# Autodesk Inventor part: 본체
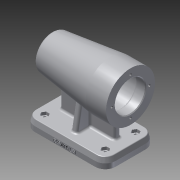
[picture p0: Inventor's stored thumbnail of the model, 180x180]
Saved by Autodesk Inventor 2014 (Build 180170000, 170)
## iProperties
Created: 2017-01
Part Number: 본체
Material: Aluminum 6061
Document SubType Name: Modeling
Designer: user
Density: 2.71 g/cm^3
Appearance: Aluminum - Flat
Mass: 797.096 g
Surface Area: 656.654 cm^2
Volume: 294.131 cm^3
Author: user
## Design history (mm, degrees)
sketch "Sketch1"
  geometry: L1 (-42, 35)-(42, 35); L2 (56, 21)-(56, -21); L3 (42, -35)-(-42, -35); L4 (-56, -21)-(-56, 21); L5 (-56, 35)-(56, -35); L6 (56, 35)-(-56, -35); A1 r 14 centre (-42, 21) between (-42, 35) and (-56, 21); A2 r 14 centre (-42, -21) between (-56, -21) and (-42, -35); A3 r 14 centre (42, -21) between (42, -35) and (56, -21); A4 r 14 centre (42, 21) between (56, 21) and (42, 35); 1 further point
  constraints: 12 end point, 8 point on circle, 8 point on line, 8 tangent, 4 centre point, 3 equal radius, 2 midpoint, 2 parallel, 1 horizontal, 1 perpendicular
  dimensions: "d0" = 112 distance of L5.end L6.end; "d1" = 70 distance of L6.start L5.end; "d2" = 14 radius of A1
extrude "Extrusion1" new body sketch "Sketch1" distance "d3" = 7; taper "d4" = 0 deg
sketch "Sketch2"
  geometry: L1 (56, -21)-(56, 21) reference; L2 (42, 35)-(-42, 35) reference; L3 (-56, 21)-(-56, -21) reference; L4 (-42, -35)-(42, -35) reference; A1 r 14 centre (42, 21) between (56, 21) and (42, 35) reference; A2 r 14 centre (-42, 21) between (-42, 35) and (-56, 21) reference; A3 r 14 centre (-42, -21) between (-56, -21) and (-42, -35) reference; A4 r 14 centre (42, -21) between (42, -35) and (56, -21) reference; 1 further point
extrude "Extrusion2" join sketch "Sketch2" distance "d5" = 7; taper "d6" = -15 deg
workplane "Work Plane1"
sketch "Sketch4"
  geometry: L1 (98, 0)-(98, 7) reference; L2 (98, 40)-(98, 108) reference; L3 (98, 108)-(70, 108); L4 (70, 108)-(184.9, 108); L5 (98, 74)-(-14, 74); L6 (70, 108)-(-10.27, 98.144); L7 (-14, 74)-(-14, 74.122); L8 (98, 0)-(84, 0) reference; A1 r 80 centre (66, 74) between (-10.27, 98.144) and (-14, 74); 1 further point
  constraints: 12 end point, 2 perpendicular, 2 point on circle, 1 centre point, 1 collinear, 1 horizontal, 1 midpoint, 1 point on line, 1 tangent, 1 vertical
  dimensions: "d7" = 68 distance of L2.start L2.end; "d8" = 28 distance of L2.end L3.end; "d11" = 160 diameter of A1; "d14" = 74 distance from line of L8 L5.start
revolve "Revolution1" sketch "Sketch4" stored, may be unused: angle "d12" = 90 deg
fillet "Fillet1" dims "d13" = 3
sketch "Sketch5"
  geometry: L1 (42, -33.124)-(-42, -33.124) reference; L2 (-4, 23)-(4, 23); L3 (4, 23)-(4, 4); L4 (4, 4)-(38, 4); L5 (38, 4)-(38, -4); L6 (38, -4)-(4, -4); L7 (4, -4)-(4, -23); L8 (4, -23)-(-4, -23); L9 (-4, -23)-(-4, -4); L10 (-4, -4)-(-38, -4); L11 (-38, -4)-(-38, 4); L12 (-38, 4)-(-4, 4); L13 (-4, 4)-(-4, 23); L14 (56, -21)-(56, 21) reference; L15 (42, 35)-(-42, 35) reference; L16 (-56, 21)-(-56, -21) reference; L17 (-42, -35)-(42, -35) reference; 1 further point
  constraints: 24 end point, 9 parallel, 3 perpendicular
  dimensions: "d15" = 8 distance of L2.start L2.end; "d16" = 8 distance of L4.end L5.end; "d17" = 8 distance of L7.end L8.end; "d18" = 8 distance of L10.end L11.end; "d19" = 52 distance from line of L14 L2.end; "d20" = 31 distance between parallel lines of L15 L4; "d21" = 31 distance between parallel lines of L15 L12; "d22" = 52 distance between parallel lines of L14 L7; "d23" = 18 distance between parallel lines of L16 L11; "d24" = 18 distance between parallel lines of L14 L5; "d25" = 12 distance between parallel lines of L15 L2; "d26" = 12 distance between parallel lines of L17 L8
extrude "Extrusion3" join sketch "Sketch5" stored distance "d27" = 7; taper "d28" = 0 deg
feature "FaceDraft1" dims angle "d29" = 10 deg
feature "FaceDraft2" dims angle "d30" = 10 deg
hole "Hole1" diameter "d33" = 21; stored, may be unused: countersink angle "d37" = 82 deg, drill point angle "d39" = 0 deg; dims "d34" = 19.05, "d35" = 9.525, "d36" = 6.35, "d38" = 106, "d40" = 25.4, "d41" = 25.4
hole "Hole2" diameter "d44" = 32; stored, may be unused: countersink angle "d48" = 82 deg, drill point angle "d50" = 0 deg; dims "d45" = 19.05, "d46" = 9.525, "d47" = 6.35, "d49" = 103, "d51" = 25.4, "d52" = 25.4
hole "Hole3" diameter "d55" = 35; stored, may be unused: countersink angle "d59" = 82 deg, drill point angle "d61" = 0 deg; dims "d56" = 19.05, "d57" = 9.525, "d58" = 6.35, "d60" = 99, "d62" = 25.4, "d63" = 25.4
hole "Hole4" diameter "d66" = 42; stored, may be unused: countersink angle "d70" = 82 deg, drill point angle "d72" = 0 deg; dims "d67" = 19.05, "d68" = 9.525, "d69" = 6.35, "d71" = 81, "d73" = 25.4, "d74" = 25.4
workplane "Work Plane2"
sketch "Sketch6"
  geometry: C1 r 21 at (0, 0) reference; C2 r 24 at (0, 0); 1 further point
  constraints: 1 centre point, 1 coincident
  dimensions: "d76" = 48 diameter of C2
extrude "Extrusion4" cut sketch "Sketch6" distance "d77" = 54; taper "d78" = 0 deg
fillet "Fillet2" dims "d79" = 0.3
fillet "Fillet3" dims "d80" = 3
chamfer "Chamfer1" distance "d81" = 1; stored, may be unused: second distance "d82" = 3.175, angle "d83" = 45 deg
fillet "Fillet4" dims "d84" = 3
fillet "Fillet5" dims "d85" = 3
fillet "Fillet6" dims "d86" = 1
sketch "Sketch7"
  geometry: C1 r 2.5 at (-42, 21); A1 r 11.357 centre (-42, 21) between (-42, 32.357) and (-53.357, 21) reference; 1 further point
  constraints: 1 centre point, 1 coincident
  dimensions: "d87" = 5 diameter of C1
extrude "Extrusion5" cut sketch "Sketch7" distance "d88" = 54; taper "d89" = 0 deg
sketch "Sketch8" dims "d90" = 10
  geometry: L1 (-39.51, 25.336)-(-37, 21.012); L2 (-37, 21.012)-(-39.49, 16.676); L3 (-39.49, 16.676)-(-44.49, 16.664); L4 (-44.49, 16.664)-(-47, 20.988); L5 (-47, 20.988)-(-44.51, 25.324); L6 (-44.51, 25.324)-(-39.51, 25.336); A1 r 11.357 centre (-42, 21) between (-42, 32.357) and (-53.357, 21) reference; 3 further points
  constraints: 12 end point, 2 coincident, 16 other
extrude "Extrusion6" cut sketch "Sketch8" distance "d91" = 4; taper "d92" = 0 deg
mirror "Mirror1"
sketch "Sketch9"
  geometry: L1 (0, 0)-(84, 0) reference; L2 (26.07, 6.019)-(57.791, 6.019); L3 (57.791, 6.019)-(57.791, 1.53); L4 (57.791, 1.53)-(26.07, 1.53); L5 (26.07, 1.53)-(26.07, 6.019); 2 further points
  constraints: 2 other
  dimensions: "d93" = 4 distance from line of L1 point (42, 4)
emboss "Emboss1" sketch "Sketch9" dims "d0" = 112, "d1" = 70, "d2" = 14, "d94" = 0.5, "d95" = 0
sketch "Sketch10" dims "d96" = 52
  geometry: L1 (0, 0)-(0, 26); C1 r 22 at (0, 0) reference; 1 further point
  constraints: 2 end point, 1 coincident, 1 vertical, 1 vertical alignment, 2 other
hole "Hole5" sketch "Sketch10" at (0, 26) diameter "d97" = 3.2512; stored, may be unused: countersink angle "d101" = 82 deg, drill point angle "d103" = 118 deg; dims "d98" = 8, "d99" = 9.525, "d100" = 6.35, "d102" = 11
pattern_circular "Circular Pattern1" dims angle "d105" = 360 deg
workplane "Work Plane4"
mirror "Mirror3"
body "Solid1"
other parameters: "d9" = 112, "d10" = 173 deg, "d75" = -15
